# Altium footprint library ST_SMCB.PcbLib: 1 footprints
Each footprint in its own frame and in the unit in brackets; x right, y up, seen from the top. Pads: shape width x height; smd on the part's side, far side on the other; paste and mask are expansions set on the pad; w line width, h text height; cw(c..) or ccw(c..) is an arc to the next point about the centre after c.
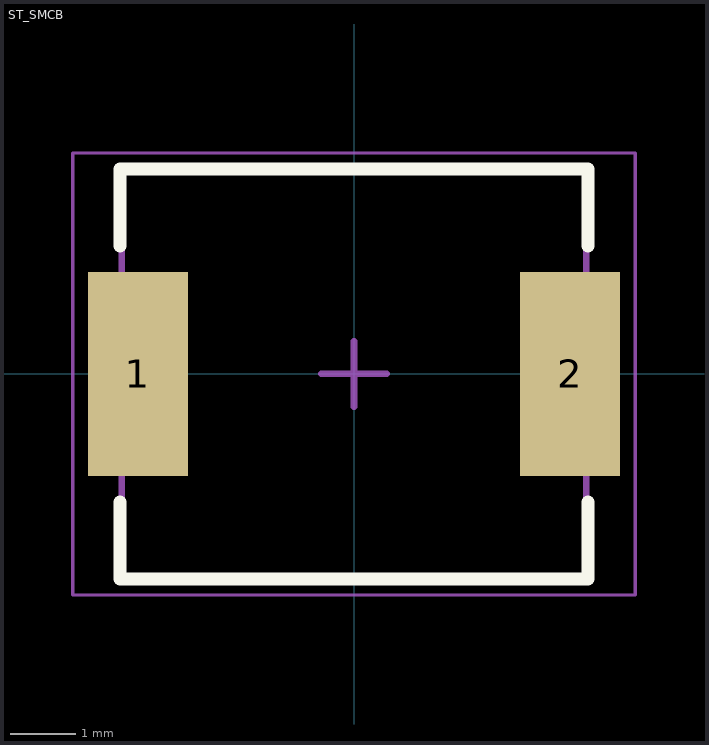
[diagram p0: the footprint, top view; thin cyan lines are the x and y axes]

## ST_SMCB [mm] "ST_SMCB"
height 2.65
pads (2):
  rect 1.54x3.14 smd: 1(-3.325,0) 2(3.325,0)
Top Overlay:
  lines w0.2: -3.6,-1.97 -3.6,-3.15 3.6,-3.15 3.6,-1.97 ; -3.6,1.97 -3.6,3.15 3.6,3.15 3.6,1.97
Mechanical 13:
  lines w0.1: -3.575,-3.125 3.575,-3.125 3.575,3.125 -3.575,3.125 -3.575,-3.125
Mechanical 15:
  lines w0.05: -4.325,-3.4 4.325,-3.4 4.325,3.4 -4.325,3.4 -4.325,-3.4
  lines w0.1: -0.5,0 0.5,0 ; 0,-0.5 0,0.5
3D body "ST_SMC.step": height 2.65, standoff 0, extent -3.795,-3.125 3.795,3.125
